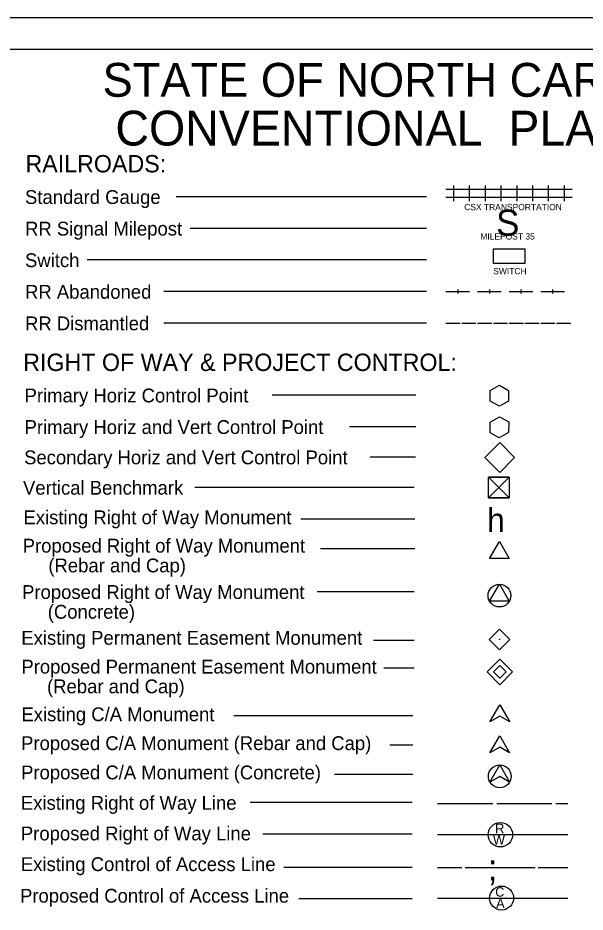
# Model space of a CAD drawing. Extents: x 2058169 to 2059852, y 675171 to 676266.
# Drawn here: x 2058730 to 2059089, y 675700 to 676266 of the extents above; entities that cross this region are included whole.
import ezdxf

# ---------------------------------------------------------------- set-up
doc = ezdxf.new("R2010")
doc.units = 0
for name, color, linetype in [('Old_Level_42', 7, 'Continuous'), ('Prop ROW Permanent Easement CELL', 7, 'Continuous'), ('Sheet Block Title CELL', 7, 'Continuous'), ('Sheet Clip Boundary CELL', 7, 'Continuous'), ('Sheet Sticker Exception Certification CELL', 7, 'Continuous'), ('Sheet Symbology CELL', 7, 'Continuous')]:
    doc.layers.add(name, color=color, linetype=linetype)

msp = doc.modelspace()

# ---------------------------------------------------------------- linework, layer by layer
at = {"layer": 'Old_Level_42'}
for p, q in [((2059034.71, 676026.77), (2059034.71, 676026.77)), ((2059034.7, 676006.81), (2059034.7, 676006.81)), ((2059034.84, 675987.73), (2059034.84, 675987.73)), ((2059034.34, 675968.73), (2059034.34, 675968.73)), ((2059034.8, 675872.51), (2059034.8, 675872.51))]:
    msp.add_line(p, q, dxfattribs=at)
for points in [[(2059034.71, 676020.12), (2059028.92, 676023.41), (2059028.92, 676030.07), (2059034.71, 676033.43), (2059040.51, 676030.14), (2059040.51, 676023.41), (2059034.71, 676020.12)], [(2059040.81, 675975.21), (2059027.84, 675962.24), (2059034.33, 675968.72), (2059040.81, 675962.24), (2059027.84, 675975.21)], [(2059034.33, 675968.72), (2059040.81, 675975.21), (2059027.84, 675975.21), (2059034.33, 675968.72)], [(2059034.33, 675968.72), (2059027.84, 675962.24), (2059040.81, 675962.24), (2059034.33, 675968.72)]]:
    msp.add_lwpolyline(points, dxfattribs=at)
for points in [[(2059028.87, 676010.18), (2059034.74, 676013.45), (2059040.6, 676010.23), (2059040.51, 676003.51), (2059034.65, 676000.1), (2059028.87, 676003.37)], [(2059025.43, 675987.76), (2059034.89, 675997.22), (2059044.36, 675987.75), (2059034.91, 675978.29)], [(2059027.84, 675975.21), (2059040.81, 675975.21), (2059040.81, 675962.24), (2059027.84, 675962.24)], [(2059028.31, 675872.51), (2059034.8, 675879.01), (2059041.3, 675872.51), (2059034.8, 675866.02)]]:
    msp.add_lwpolyline(points, close=True, dxfattribs=at)
msp.add_circle((2059034.8, 675872.51), 0.126, dxfattribs=at)
at = {"layer": 'Prop ROW Permanent Easement CELL'}
msp.add_line((2059034.98, 675851.91), (2059034.98, 675851.91), dxfattribs=at)
for points in [[(2059034.98, 675859.96), (2059043.03, 675851.9), (2059034.98, 675843.85), (2059026.93, 675851.9)], [(2059034.98, 675855.93), (2059039.01, 675851.9), (2059034.98, 675847.88), (2059030.96, 675851.9)]]:
    msp.add_lwpolyline(points, close=True, dxfattribs=at)
at = {"layer": 'Sheet Block Title CELL'}
msp.add_lwpolyline([(2058181.51, 675191.07), (2059847.5, 675191.08), (2059847.51, 676246.07), (2058181.51, 676246.07)], close=True, dxfattribs=at)
at = {"layer": 'Sheet Clip Boundary CELL'}
msp.add_line((2059852.01, 676266.07), (2058168.51, 676266.07), dxfattribs=at)
at = {"layer": 'Sheet Sticker Exception Certification CELL'}
msp.add_lwpolyline([(2058168.51, 675171.07), (2059852.01, 675171.07), (2059852.01, 676266.07), (2058168.51, 676266.07)], close=True, dxfattribs=at)
at = {"layer": 'Sheet Symbology CELL'}
for p, q in [((2059000.87, 676157.53), (2059010.87, 676157.53)), ((2059005.87, 676150.03), (2059005.87, 676160.03)), ((2059010.87, 676157.53), (2059020.87, 676157.53)), ((2059015.87, 676150.03), (2059015.87, 676160.03)), ((2059020.87, 676157.53), (2059030.87, 676157.53)), ((2059025.87, 676150.03), (2059025.87, 676160.03)), ((2059030.87, 676157.53), (2059040.87, 676157.53)), ((2059035.87, 676150.03), (2059035.87, 676160.03)), ((2059040.87, 676157.53), (2059050.87, 676157.53)), ((2059045.87, 676150.03), (2059045.87, 676160.03)), ((2059050.87, 676157.53), (2059060.87, 676157.53)), ((2059055.87, 676150.03), (2059055.87, 676160.03)), ((2059060.87, 676157.53), (2059070.87, 676157.53)), ((2059065.87, 676150.03), (2059065.87, 676160.03)), ((2059070.87, 676157.53), (2059080.87, 676157.53)), ((2059075.87, 676150.03), (2059075.87, 676160.03)), ((2058988.47, 676152.77), (2058830.06, 676152.77)), ((2059000.87, 676152.53), (2059010.87, 676152.53)), ((2059010.87, 676152.53), (2059020.87, 676152.53)), ((2059020.87, 676152.53), (2059030.87, 676152.53)), ((2059030.87, 676152.53), (2059040.87, 676152.53)), ((2059040.87, 676152.53), (2059050.87, 676152.53)), ((2059050.87, 676152.53), (2059060.87, 676152.53)), ((2059060.87, 676152.53), (2059070.87, 676152.53)), ((2059070.87, 676152.53), (2059080.87, 676152.53)), ((2058988.47, 676132.77), (2058838.92, 676132.77)), ((2058988.47, 676112.77), (2058773.56, 676112.77)), ((2058988.47, 676092.77), (2058822.31, 676092.77)), ((2059000.87, 676092.77), (2059015.87, 676092.77)), ((2059008.37, 676094.02), (2059008.37, 676091.52)), ((2059020.87, 676092.77), (2059035.87, 676092.77)), ((2059028.37, 676094.02), (2059028.37, 676091.52)), ((2059040.87, 676092.77), (2059055.87, 676092.77)), ((2059048.37, 676094.02), (2059048.37, 676091.52)), ((2059060.87, 676092.77), (2059075.87, 676092.77)), ((2059068.37, 676094.02), (2059068.37, 676091.52)), ((2058988.47, 676072.77), (2058822.31, 676072.77)), ((2058988.47, 676072.77), (2058822.31, 676072.77)), ((2059000.87, 676072.77), (2059009.87, 676072.77)), ((2059010.87, 676072.77), (2059019.87, 676072.77)), ((2059020.87, 676072.77), (2059029.87, 676072.77)), ((2059030.87, 676072.77), (2059039.87, 676072.77)), ((2059040.87, 676072.77), (2059049.87, 676072.77)), ((2059050.87, 676072.77), (2059059.87, 676072.77)), ((2059060.87, 676072.77), (2059069.87, 676072.77)), ((2059070.87, 676072.77), (2059079.87, 676072.77)), ((2058981.78, 676027.15), (2058890.75, 676027.15)), ((2058981.78, 676007.15), (2058939.86, 676007.15)), ((2058981.47, 675987.94), (2058952.92, 675987.94)), ((2058980.78, 675968.72), (2058841.94, 675968.72)), ((2058981.09, 675948.74), (2058909.04, 675948.74)), ((2058981.19, 675929.95), (2058921.46, 675929.95)), ((2059034.71, 675927.34), (2059034.71, 675927.34)), ((2058980.69, 675902.55), (2058919.2, 675902.55)), ((2059034.73, 675900.28), (2059034.73, 675900.28)), ((2058980.77, 675871.86), (2058954.98, 675871.86)), ((2058980.77, 675854.24), (2058961.49, 675854.24)), ((2059028.71, 675820.33), (2059034.96, 675831.13)), ((2059034.96, 675831.13), (2059041.21, 675820.33)), ((2058979.78, 675824.02), (2058866.54, 675824.02)), ((2059034.96, 675823.93), (2059028.71, 675820.33)), ((2059041.21, 675820.33), (2059034.96, 675823.93)), ((2059028.68, 675800.72), (2059034.93, 675811.52)), ((2059034.93, 675811.52), (2059041.18, 675800.72)), ((2058979.88, 675805.48), (2058965.31, 675805.48)), ((2059034.93, 675804.32), (2059028.68, 675800.72)), ((2059041.18, 675800.72), (2059034.93, 675804.32)), ((2059028.68, 675782.21), (2059034.93, 675793.01)), ((2059034.93, 675793.01), (2059041.18, 675782.21)), ((2058979.88, 675786.98), (2058930.21, 675786.98)), ((2059034.93, 675785.81), (2059028.68, 675782.21)), ((2059041.18, 675782.21), (2059034.93, 675785.81)), ((2058979.44, 675769.2), (2058876.92, 675769.2)), ((2058995.47, 675768.62), (2059030.47, 675768.62)), ((2059032.97, 675768.62), (2059067.97, 675768.62)), ((2059070.47, 675768.62), (2059077.97, 675768.62)), ((2058979.44, 675749.2), (2058884.91, 675749.2)), ((2058995.47, 675749.07), (2059077.97, 675749.07)), ((2058979.44, 675728.07), (2058898.12, 675728.07)), ((2058995.47, 675728.07), (2059010.93, 675728.07)), ((2059012.93, 675728.07), (2059057.34, 675728.07)), ((2059059.34, 675728.07), (2059077.97, 675728.07)), ((2058979.44, 675708.26), (2058907.79, 675708.26)), ((2058995.47, 675708.64), (2059077.97, 675708.64))]:
    msp.add_line(p, q, dxfattribs=at)
for points in [[(2059030.87, 676119.73), (2059050.87, 676119.73), (2059050.87, 676110.63), (2059030.87, 676110.63)], [(2059028.46, 675923.74), (2059034.71, 675934.54), (2059040.96, 675923.74)], [(2059028.48, 675896.68), (2059034.73, 675907.48), (2059040.98, 675896.68)]]:
    msp.add_lwpolyline(points, close=True, dxfattribs=at)
for centre, radius in [((2059034.72, 675900.27), 7.2), ((2059034.93, 675785.81), 7.2), ((2059035.32, 675748.87), 7.75), ((2059036.11, 675708.74), 7.58)]:
    msp.add_circle(centre, radius, dxfattribs=at)

# ---------------------------------------------------------------- texts
for s, height, p in [('STATE OF NORTH CAROLINA, DIVISION OF HIGHWAYS', 21.419, (2058783.41, 676216.12)), ('CONVENTIONAL  PLAN SHEET SYMBOLS', 22.0323, (2058791.54, 676185.24)), ('RAILROADS:', 11, (2058734.59, 676168.22)), ('Standard Gauge', 8.75, (2058734.31, 676148.24)), ('CSX TRANSPORTATION', 4, (2059012.43, 676144.29)), ('S', 16.5, (2059032.63, 676128.14)), ('RR Signal Milepost', 8.75, (2058734.31, 676128.24)), ('MILEPOST 35', 4, (2059022.62, 676125.72)), ('Switch', 8.75, (2058734.31, 676108.24)), ('SWITCH', 4, (2059030.82, 676103.72)), ('RR Abandoned', 8.75, (2058734.31, 676088.24)), ('RR Dismantled', 8.75, (2058734.31, 676068.24)), ('RIGHT OF WAY & PROJECT CONTROL:', 11, (2058733.18, 676042.49)), ('Primary Horiz Control Point', 8.75, (2058734.03, 676022.6)), ('Primary Horiz and Vert Control Point', 8.75, (2058734.03, 676002.6)), ('Secondary Horiz and Vert Control Point', 8.75, (2058733.72, 675983.39)), ('Vertical Benchmark', 8.75, (2058733.03, 675964.17)), ('h', 15, (2059026.94, 675940.56)), ('Existing Right of Way Monument', 8.75, (2058733.34, 675945.46)), ('Proposed Right of Way Monument', 8.75, (2058732.82, 675927.48)), ('     (Rebar and Cap)', 8.75, (2058732.82, 675914.98)), ('Proposed Right of Way Monument', 8.75, (2058732.45, 675898.13)), ('     (Concrete)', 8.75, (2058732.45, 675885.63)), ('Existing Permanent Easement Monument', 8.75, (2058731.96, 675869.14)), ('Proposed Permanent Easement Monument', 8.75, (2058732, 675850.91)), ('     (Rebar and Cap)', 8.75, (2058732, 675838.41)), ('Existing C/A Monument', 8.75, (2058732.03, 675820.74)), ('Proposed C/A Monument (Rebar and Cap)', 8.75, (2058731.82, 675802.43)), ('Proposed C/A Monument (Concrete)', 8.75, (2058731.82, 675783.92)), ('Existing Right of Way Line', 8.75, (2058731.69, 675764.65)), ('Proposed Right of Way Line', 8.75, (2058731.69, 675745.27)), ('R', 6.07, (2059031.98, 675749.78)), ('W', 6.07, (2059030.6, 675742.62)), ('Existing Control of Access Line', 8.75, (2058731.69, 675725.81)), (';', 16.5, (2059027.26, 675719.89)), ('Proposed Control of Access Line', 8.75, (2058731.14, 675705.83)), ('C', 5.94, (2059032.08, 675709.64)), ('A', 5.94, (2059032.68, 675702.5))]:
    msp.add_text(s, height=height, rotation=360, dxfattribs=at).set_placement(p)

doc.saveas('drawing.dxf')
